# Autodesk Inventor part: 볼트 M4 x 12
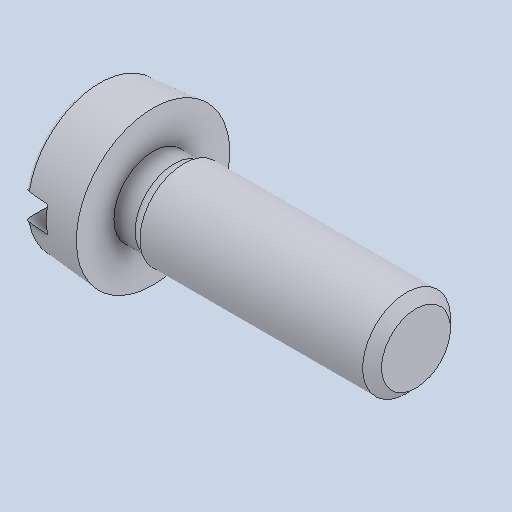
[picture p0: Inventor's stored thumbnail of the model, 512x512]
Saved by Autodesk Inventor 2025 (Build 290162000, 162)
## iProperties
Created: 2024-07
Part Number: 볼트 M4 x 12
Material: 강철, 연강
Description: 6각머리 태핑 나사
Document SubType Name: Modeling
Designer: onair
Density: 7.85 g/cm^3
Appearance: 기본값
Author: jhkim
Sending System: Autodesk Inventor 2025
Preprocessor: ST-DEVELOPER v20
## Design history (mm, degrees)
feature "Solid1"
node "솔리드1"
